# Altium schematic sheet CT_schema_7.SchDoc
size 278 x 170 mm
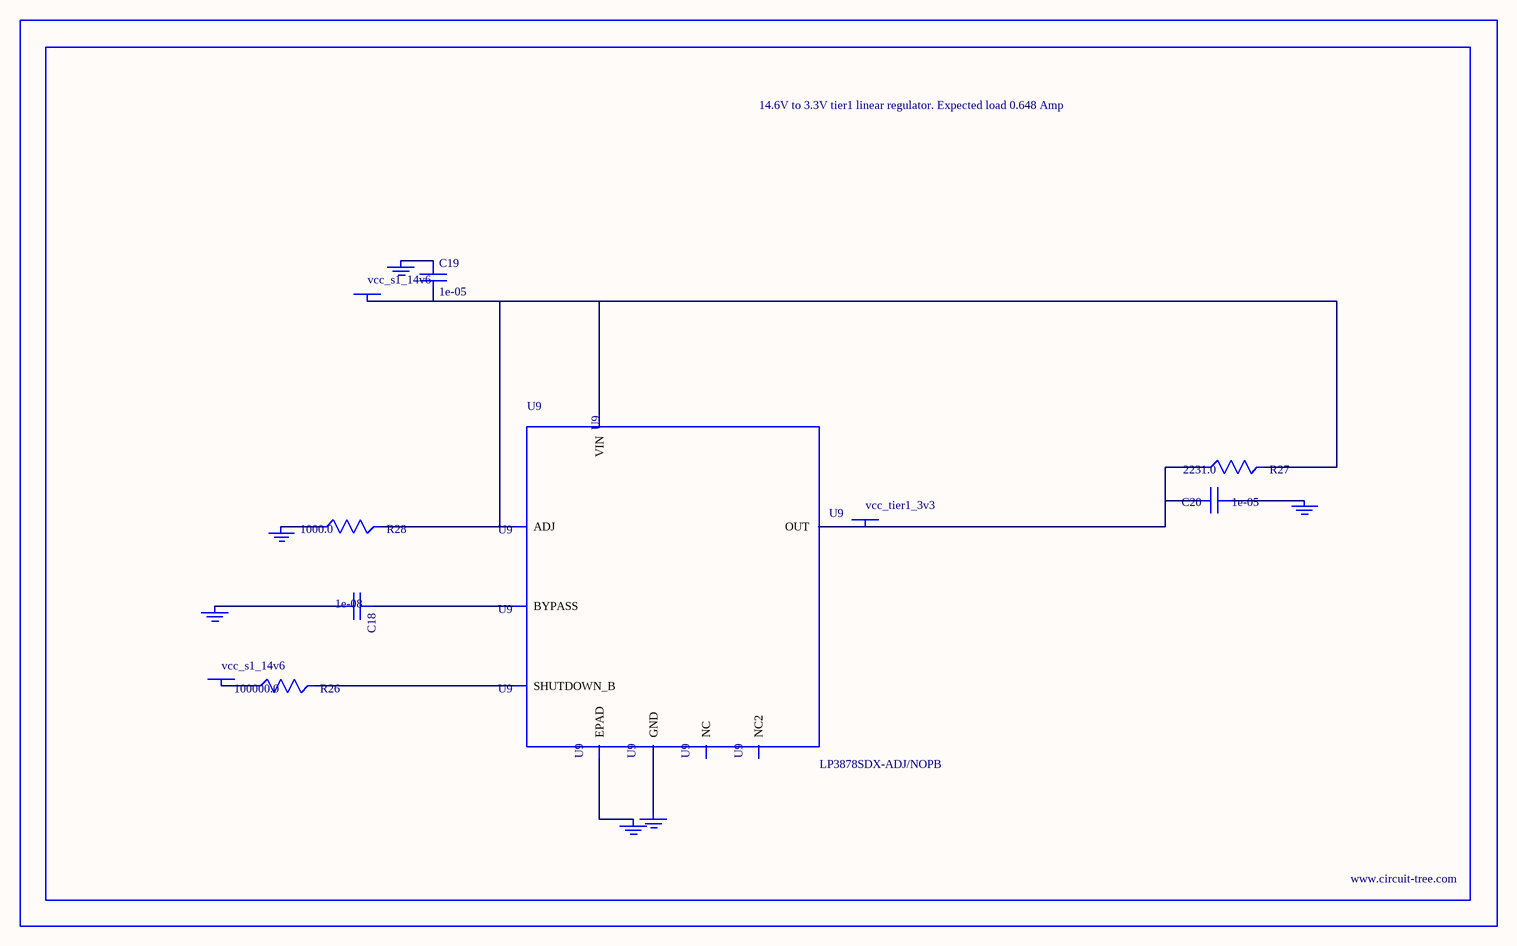
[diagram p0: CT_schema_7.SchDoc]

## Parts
BORDER6  (no value)
C18  1e-08  [C0402]
C19  1e-05  [C1210]
C20  1e-05  [C1210]
GND_INSTANCE_6_0  (no value)
GND_INSTANCE_6_1  (no value)
GND_INSTANCE_6_2  (no value)
GND_INSTANCE_6_3  (no value)
GND_INSTANCE_6_4  (no value)
GND_INSTANCE_6_5  (no value)
POWER_INSTANCE_6_0  vcc_s1_14v6
POWER_INSTANCE_6_1  vcc_s1_14v6
POWER_INSTANCE_6_2  vcc_tier1_3v3
R26  100000.0  [R0603]
R27  2231.0  [R0603]
R28  1000.0  [R0603]
U9  LP3878SDX-ADJ/NOPB  [WSON-8]

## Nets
NetC18_1: C18.1 U9.1(BYPASS)
NetC18_2: C18.2 GND_INSTANCE_6_0.0(GND)
NetC19_1: C19.1 GND_INSTANCE_6_1.0(GND)
NetC19_2: C19.2 POWER_INSTANCE_6_0.0(PWR) R27.2 R28.2 U9.4(VIN) U9.6(ADJ)
NetC20_1: C20.1 GND_INSTANCE_6_2.0(GND)
NetC20_2: C20.2 POWER_INSTANCE_6_2.0(PWR) R27.1 U9.5(OUT)
NetGND_INSTANCE_6_3_0: GND_INSTANCE_6_3.0(GND) R28.1
NetGND_INSTANCE_6_4_0: GND_INSTANCE_6_4.0(GND) U9.PAD(EPAD)
NetGND_INSTANCE_6_5_0: GND_INSTANCE_6_5.0(GND) U9.3(GND)
NetPOWER_INSTANCE_6_1_0: POWER_INSTANCE_6_1.0(PWR) R26.1
NetR26_2: R26.2 U9.8(SHUTDOWN_B)

Not connected (* = marked no-connect by the designer): U9 2(NC) 7(NC2)

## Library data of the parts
BORDER6 = BORDER_PAGE6
C18 = C0402C103K3RAC
C19 = C1210C106K5PACTU
C20 = GRM32DR61E106MA12L
GND_INSTANCE_6_0-GND_INSTANCE_6_5 = GND
POWER_INSTANCE_6_0-POWER_INSTANCE_6_2 = PWR
R26 = RC0603JR-07100KL
R27 = R27
R28 = RC0603JR-071KL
